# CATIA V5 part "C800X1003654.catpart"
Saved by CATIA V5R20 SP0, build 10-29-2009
Part number: C800X1003654
Source: Unknown
Property "A": "50"
Property "ARTICLENO": "C800X1003654"
Property "B": "23"
Property "BOMINFO": "C800X1003654"
Property "C": "91"
Property "CA": "C800X1003654"
Property "D1": "90"
Property "DES": "ROTATING EYEBOLT WITH RING Ton 10,0 M36x54"
Property "E": "86"
Property "H": "200"
Property "L": "54"
Property "LINA": "C800X1003654"
Property "NB": "C800X1003654"
Property "NBSYN": "$CODE."
Property "NN": "C800X"
Property "NT": "Rotating eyebolt with ring"
Property "SIZE": "M36"
Property "SUPPLIER": "CF"
Property "SW": "80"
Property "WEIGHT": "4620"
Property "WLL": "10.00"
Bounding box of the stored display mesh (mm): x -47.825 to 48, y -54 to 222.825, z -45 to 45
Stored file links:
  C:\Users\Utente\Desktop\3D files 800X\C800X1003654.catpart

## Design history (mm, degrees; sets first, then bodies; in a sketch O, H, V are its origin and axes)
Body1 "Geometry.1" (main body)
  Solid1 "C800X1003654.catpart": solid without history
